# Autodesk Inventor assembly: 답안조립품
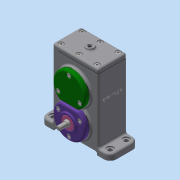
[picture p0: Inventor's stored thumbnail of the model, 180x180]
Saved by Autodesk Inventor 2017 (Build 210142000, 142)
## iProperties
Part Number: 답안조립품
Material: 일반
Document SubType Name: Assembly
Designer: 222
Mass: 1460.95 g
Surface Area: 1575.48 cm^2
Volume: 385.032 cm^3
Density: 3.79437 g/cm^3
Author: 222
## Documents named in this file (24)
- C:\Users\222\Desktop\600506V1018\답안조립품.iam
- C:\Users\222\Desktop\600506V1018\본체.ipt
- C:\Users\222\Desktop\600506V1018\Ű 4 x 4 x 12.ipt
- C:\Users\222\Desktop\600506V1018\Ű 5 x 5 x 12.ipt
- C:\Users\222\Desktop\600506V1018\개스킷 A.ipt
- C:\Users\222\Desktop\600506V1018\개스킷 B.ipt
- C:\Users\222\Desktop\600506V1018\개스킷 C.ipt
- C:\Users\222\Desktop\600506V1018\베어링 6001.ipt
- 베어링 6001.ipt
- C:\Users\222\Desktop\600506V1018\베어링 6002.ipt
- 베어링 6002.ipt
- C:\Users\222\Desktop\600506V1018\볼트 M4.ipt
- C:\Users\222\Desktop\600506V1018\스퍼기어 A.ipt
- C:\Users\222\Desktop\600506V1018\스퍼기어 B.ipt
- C:\Users\222\Desktop\600506V1018\오일 실 10 20 7.ipt
- C:\Users\222\Desktop\600506V1018\오일 실 12 22 7.ipt
- C:\Users\222\Desktop\600506V1018\축 A.ipt
- C:\Users\222\Desktop\600506V1018\축 B.ipt
- C:\Users\222\Desktop\600506V1018\칼라.ipt
- C:\Users\222\Desktop\600506V1018\커버 A.ipt
- C:\Users\222\Desktop\600506V1018\커버 B.ipt
- C:\Users\222\Desktop\600506V1018\커버 C.ipt
- C:\Users\222\Desktop\600506V1018\커버 D.ipt
- C:\Users\222\Desktop\600506V1018\커버 E.ipt
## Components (7 placed, 5 different names)
1. Ű 4 x 4 x 12:1
2. Ű 5 x 5 x 12:1
3. 개스킷 A:1
4. 개스킷 B:1
5. 개스킷 C:1
6. 개스킷 B:2
7. 개스킷 B:3
